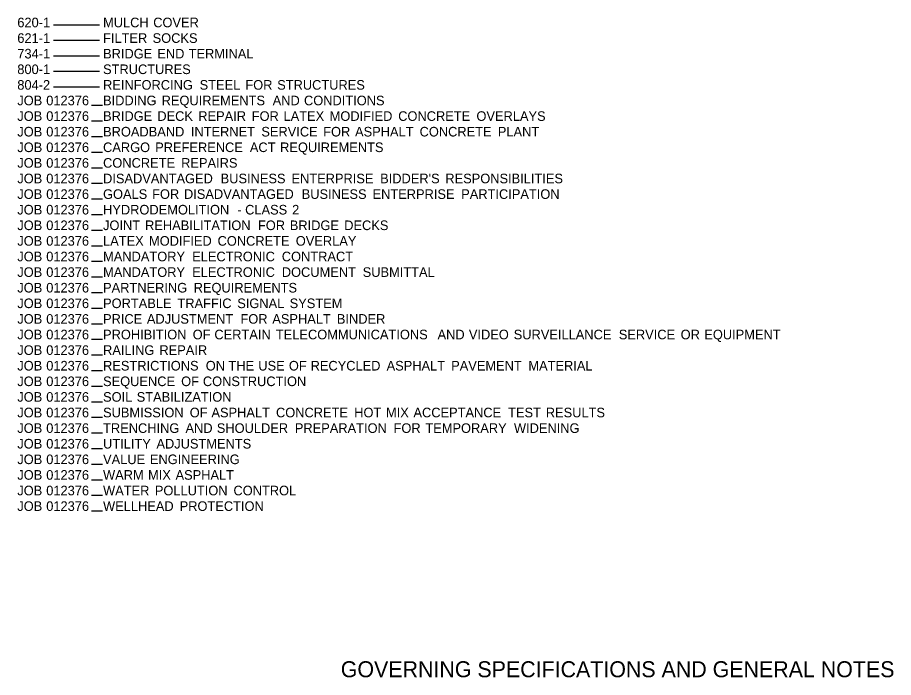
# Model space of a CAD drawing. Extents: x 1930579 to 1935779, y 596313 to 597298.
# Drawn here: x 1935090 to 1935747, y 596313 to 596808 of the extents above; entities that cross this region are included whole.
import ezdxf

# ---------------------------------------------------------------- set-up
doc = ezdxf.new("R2010")
doc.units = 0
doc.layers.add('Default', color=7, linetype='Continuous')
doc.layers.add('R_Border', color=7, linetype='Continuous')

msp = doc.modelspace()

# ---------------------------------------------------------------- linework, layer by layer
at = {"layer": 'R_Border'}
for p, q in [((1935116.78, 596802.56), (1935151.47, 596802.56)), ((1935116.78, 596790.91), (1935151.47, 596790.91)), ((1935116.78, 596779.26), (1935151.47, 596779.26)), ((1935116.78, 596767.62), (1935151.47, 596767.62)), ((1935116.78, 596755.97), (1935151.47, 596755.97)), ((1935145.46, 596742.11), (1935153.68, 596742.11)), ((1935145.46, 596730.41), (1935153.68, 596730.41)), ((1935145.46, 596718.71), (1935153.68, 596718.71)), ((1935145.46, 596707.01), (1935153.68, 596707.01)), ((1935145.46, 596695.31), (1935153.68, 596695.31)), ((1935145.46, 596683.61), (1935153.68, 596683.61)), ((1935145.46, 596671.91), (1935153.68, 596671.91)), ((1935145.46, 596660.21), (1935153.68, 596660.21)), ((1935145.46, 596648.51), (1935153.68, 596648.51)), ((1935145.46, 596636.81), (1935153.68, 596636.81)), ((1935145.46, 596625.11), (1935153.68, 596625.11)), ((1935145.46, 596613.41), (1935153.68, 596613.41)), ((1935145.46, 596601.71), (1935153.68, 596601.71)), ((1935145.46, 596590.01), (1935153.68, 596590.01)), ((1935145.46, 596578.31), (1935153.68, 596578.31)), ((1935145.46, 596566.61), (1935153.68, 596566.61)), ((1935145.46, 596554.91), (1935153.68, 596554.91)), ((1935145.46, 596543.21), (1935153.68, 596543.21)), ((1935145.46, 596531.51), (1935153.68, 596531.51)), ((1935145.46, 596519.81), (1935153.68, 596519.81)), ((1935145.46, 596508.11), (1935153.68, 596508.11)), ((1935145.46, 596496.41), (1935153.68, 596496.41)), ((1935145.46, 596484.71), (1935153.68, 596484.71)), ((1935145.46, 596473.01), (1935153.68, 596473.01)), ((1935145.46, 596461.31), (1935153.68, 596461.31)), ((1935145.46, 596449.61), (1935153.68, 596449.61)), ((1935145.46, 596437.91), (1935153.68, 596437.91))]:
    msp.add_line(p, q, dxfattribs=at)

# ---------------------------------------------------------------- texts
at = {"layer": 'Default'}
for s, p in [('620-1', (1935089.75, 596800.61)), ('MULCH', (1935154.1, 596800.61)), (' COVER', (1935189.06, 596800.61)), ('621-1', (1935089.75, 596788.91)), ('FILTER', (1935154.1, 596788.91)), (' SOCKS', (1935188.62, 596788.91)), ('734-1', (1935089.75, 596777.21)), ('BRIDGE', (1935154.1, 596777.21)), (' END', (1935192.14, 596777.21)), (' TERMINAL', (1935215.64, 596777.21)), ('800-1', (1935089.75, 596765.51)), ('STRUCTURES', (1935154.1, 596765.51)), ('804-2', (1935089.75, 596753.81)), ('REINFORCING', (1935154.1, 596753.81)), (' STEEL', (1935223.9, 596753.81)), (' FOR', (1935258.21, 596753.81)), (' STRUCTURES', (1935282.1, 596753.81)), ('JOB', (1935089.75, 596742.11)), (' 012376', (1935108.78, 596742.11)), ('BIDDING', (1935154.1, 596742.11)), (' REQUIREMENTS', (1935195.39, 596742.11)), (' AND', (1935278.71, 596742.11)), (' CONDITIONS', (1935302.21, 596742.11)), ('JOB', (1935089.75, 596730.41)), (' 012376', (1935108.78, 596730.41)), ('BRIDGE', (1935154.1, 596730.41)), (' DECK', (1935192.14, 596730.41)), (' REPAIR', (1935222.86, 596730.41)), (' FOR', (1935262.98, 596730.41)), (' LATEX', (1935286.87, 596730.41)), (' MODIFIED', (1935321.48, 596730.41)), (' CONCRETE', (1935372.91, 596730.41)), (' OVERLAYS', (1935431.63, 596730.41)), ('JOB', (1935089.75, 596718.71)), (' 012376', (1935108.78, 596718.71)), ('BROADBAND', (1935154.1, 596718.71)), (' INTERNET', (1935217.3, 596718.71)), (' SERVICE', (1935270.2, 596718.71)), (' FOR', (1935316.62, 596718.71)), (' ASPHALT', (1935340.52, 596718.71)), (' CONCRETE', (1935388.96, 596718.71)), (' PLANT', (1935447.67, 596718.71)), ('JOB', (1935089.75, 596707.01)), (' 012376', (1935108.78, 596707.01)), ('CARGO', (1935154.1, 596707.01)), (' PREFERENCE', (1935190.55, 596707.01)), (' ACT', (1935261.57, 596707.01)), (' REQUIREMENTS', (1935284.28, 596707.01)), ('JOB', (1935089.75, 596695.31)), (' 012376', (1935108.78, 596695.31)), ('CONCRETE', (1935154.1, 596695.31)), (' REPAIRS', (1935210.02, 596695.31)), ('JOB', (1935089.75, 596683.61)), (' 012376', (1935108.78, 596683.61)), ('DISADVANTAGED', (1935154.1, 596683.61)), (' BUSINESS', (1935239.66, 596683.61)), (' ENTERPRISE', (1935292.81, 596683.61)), (" BIDDER'S", (1935359.36, 596683.61)), (' RESPONSIBILITIES', (1935408.28, 596683.61)), ('JOB', (1935089.75, 596671.91)), (' 012376', (1935108.78, 596671.91)), ('GOALS', (1935154.1, 596671.91)), (' FOR', (1935188.24, 596671.91)), (' DISADVANTAGED', (1935212.14, 596671.91)), (' BUSINESS', (1935300.49, 596671.91)), (' ENTERPRISE', (1935353.64, 596671.91)), (' PARTICIPATION', (1935420.19, 596671.91)), ('JOB', (1935089.75, 596660.21)), (' 012376', (1935108.78, 596660.21)), ('HYDRODEMOLITION', (1935154.1, 596660.21)), (' -', (1935252.21, 596660.21)), (' CLASS', (1935258.04, 596660.21)), (' 2', (1935293.3, 596660.21)), ('JOB', (1935089.75, 596648.51)), (' 012376', (1935108.78, 596648.51)), ('JOINT', (1935154.1, 596648.51)), (' REHABILITATION', (1935182.96, 596648.51)), (' FOR', (1935267.67, 596648.51)), (' BRIDGE', (1935291.56, 596648.51)), (' DECKS', (1935332.39, 596648.51)), ('JOB', (1935089.75, 596636.81)), (' 012376', (1935108.78, 596636.81)), ('LATEX', (1935154.1, 596636.81)), (' MODIFIED', (1935185.91, 596636.81)), (' CONCRETE', (1935237.35, 596636.81)), (' OVERLAY', (1935296.06, 596636.81)), ('JOB', (1935089.75, 596625.11)), (' 012376', (1935108.78, 596625.11)), ('MANDATORY', (1935154.1, 596625.11)), (' ELECTRONIC', (1935218.31, 596625.11)), (' CONTRACT', (1935285.55, 596625.11)), ('JOB', (1935089.75, 596613.41)), (' 012376', (1935108.78, 596613.41)), ('MANDATORY', (1935154.1, 596613.41)), (' ELECTRONIC', (1935218.31, 596613.41)), (' DOCUMENT', (1935285.55, 596613.41)), (' SUBMITTAL', (1935346.26, 596613.41)), ('JOB', (1935089.75, 596601.71)), (' 012376', (1935108.78, 596601.71)), ('PARTNERING', (1935154.1, 596601.71)), (' REQUIREMENTS', (1935219.43, 596601.71)), ('JOB', (1935089.75, 596590.01)), (' 012376', (1935108.78, 596590.01)), ('PORTABLE', (1935154.1, 596590.01)), (' TRAFFIC', (1935207.24, 596590.01)), (' SIGNAL', (1935252.11, 596590.01)), (' SYSTEM', (1935291.45, 596590.01)), ('JOB', (1935089.75, 596578.31)), (' 012376', (1935108.78, 596578.31)), ('PRICE', (1935154.1, 596578.31)), (' ADJUSTMENT', (1935184.31, 596578.31)), (' FOR', (1935254.54, 596578.31)), (' ASPHALT', (1935278.43, 596578.31)), (' BINDER', (1935326.88, 596578.31)), ('JOB', (1935089.75, 596566.61)), (' 012376', (1935108.78, 596566.61)), ('PROHIBITION', (1935154.1, 596566.61)), (' OF', (1935218.68, 596566.61)), (' CERTAIN', (1935234.98, 596566.61)), (' TELECOMMUNICATIONS', (1935281.11, 596566.61)), (' AND', (1935402.44, 596566.61)), (' VIDEO', (1935425.94, 596566.61)), (' SURVEILLANCE', (1935459.59, 596566.61)), (' SERVICE', (1935538.44, 596566.61)), (' OR', (1935584.87, 596566.61)), (' EQUIPMENT', (1935602.62, 596566.61)), ('JOB', (1935089.75, 596554.91)), (' 012376', (1935108.78, 596554.91)), ('RAILING', (1935154.1, 596554.91)), (' REPAIR', (1935193.72, 596554.91)), ('JOB', (1935089.75, 596543.21)), (' 012376', (1935108.78, 596543.21)), ('RESTRICTIONS', (1935154.1, 596543.21)), (' ON', (1935228.48, 596543.21)), (' THE', (1935245.54, 596543.21)), (' USE', (1935267.92, 596543.21)), (' OF', (1935290.86, 596543.21)), (' RECYCLED', (1935307.17, 596543.21)), (' ASPHALT', (1935364.21, 596543.21)), (' PAVEMENT', (1935412.65, 596543.21)), (' MATERIAL', (1935470.6, 596543.21)), ('JOB', (1935089.75, 596531.51)), (' 012376', (1935108.78, 596531.51)), ('SEQUENCE', (1935154.1, 596531.51)), (' OF', (1935210.03, 596531.51)), (' CONSTRUCTION', (1935226.34, 596531.51)), ('JOB', (1935089.75, 596519.81)), (' 012376', (1935108.78, 596519.81)), ('SOIL', (1935154.1, 596519.81)), (' STABILIZATION', (1935176.67, 596519.81)), ('JOB', (1935089.75, 596508.11)), (' 012376', (1935108.78, 596508.11)), ('SUBMISSION', (1935154.1, 596508.11)), (' OF', (1935216.45, 596508.11)), (' ASPHALT', (1935232.75, 596508.11)), (' CONCRETE', (1935281.19, 596508.11)), (' HOT', (1935339.91, 596508.11)), (' MIX', (1935363.74, 596508.11)), (' ACCEPTANCE', (1935384.35, 596508.11)), (' TEST', (1935455.37, 596508.11)), (' RESULTS', (1935483.68, 596508.11)), ('JOB', (1935089.75, 596496.41)), (' 012376', (1935108.78, 596496.41)), ('TRENCHING', (1935154.1, 596496.41)), (' AND', (1935213.28, 596496.41)), (' SHOULDER', (1935236.78, 596496.41)), (' PREPARATION', (1935295.34, 596496.41)), (' FOR', (1935369.43, 596496.41)), (' TEMPORARY', (1935393.32, 596496.41)), (' WIDENING', (1935459.77, 596496.41)), ('JOB', (1935089.75, 596484.71)), (' 012376', (1935108.78, 596484.71)), ('UTILITY', (1935154.1, 596484.71)), (' ADJUSTMENTS', (1935191.47, 596484.71)), ('JOB', (1935089.75, 596473.01)), (' 012376', (1935108.78, 596473.01)), ('VALUE', (1935154.1, 596473.01)), (' ENGINEERING', (1935186.56, 596473.01)), ('JOB', (1935089.75, 596461.31)), (' 012376', (1935108.78, 596461.31)), ('WARM', (1935154.1, 596461.31)), (' MIX', (1935185.2, 596461.31)), (' ASPHALT', (1935205.81, 596461.31)), ('JOB', (1935089.75, 596449.61)), (' 012376', (1935108.78, 596449.61)), ('WATER', (1935154.1, 596449.61)), (' POLLUTION', (1935190.29, 596449.61)), (' CONTROL', (1935249.28, 596449.61)), ('JOB', (1935089.75, 596437.91)), (' 012376', (1935108.78, 596437.91)), ('WELLHEAD', (1935154.1, 596437.91)), (' PROTECTION', (1935208.91, 596437.91))]:
    msp.add_text(s, height=7.2, dxfattribs=at).set_placement(p)
at = {"layer": 'R_Border'}
msp.add_text('GOVERNING SPECIFICATIONS AND GENERAL NOTES ', height=12, rotation=360, dxfattribs=at).set_placement((1935332.49, 596313.19))

doc.saveas('drawing.dxf')
